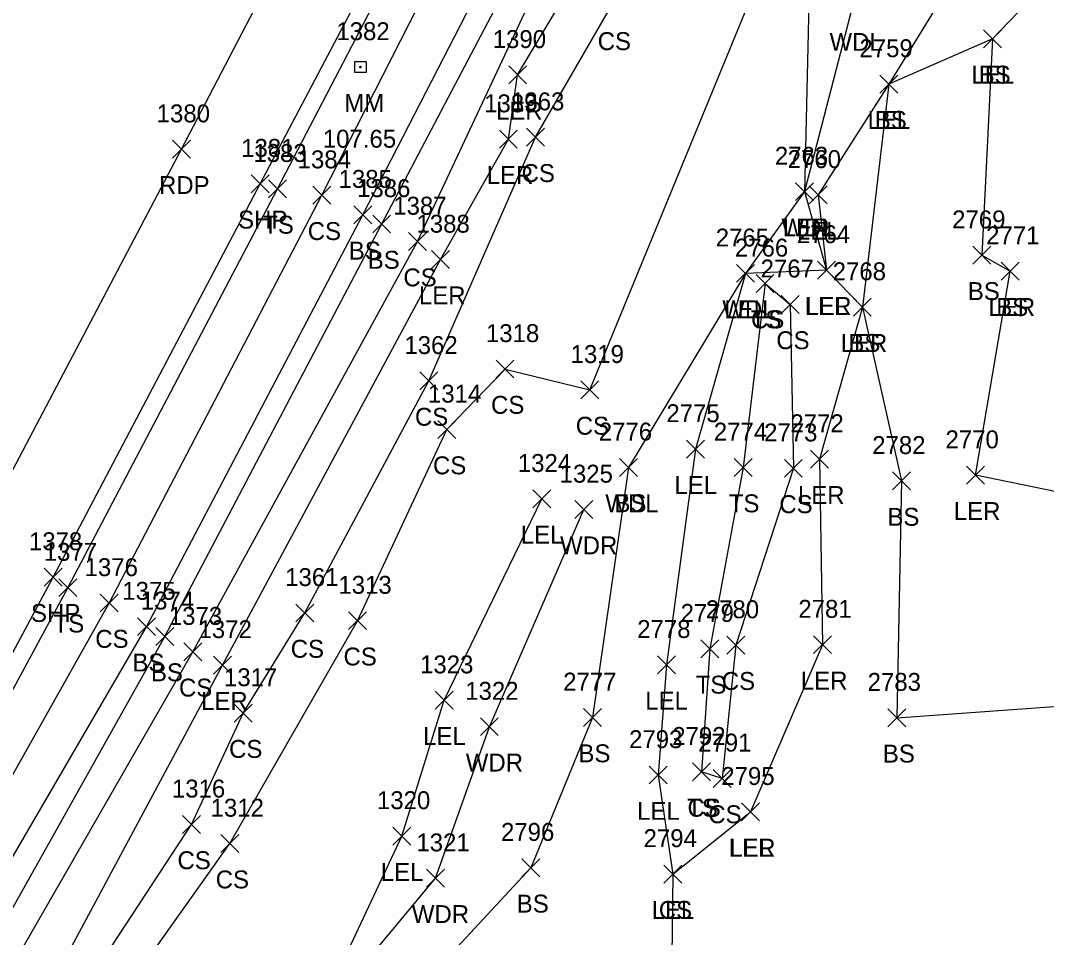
# Model space of a CAD drawing. Extents: x 1483143 to 1488182, y 802902 to 807581.
# Drawn here: x 1487426.2 to 1487540.6, y 805492.2 to 805594.5 of the extents above; entities that cross this region are included whole.
import ezdxf

# ---------------------------------------------------------------- set-up
doc = ezdxf.new("R2010")
doc.units = 0
for name, color, linetype in [('L_A', 7, 'Continuous'), ('L_I', 7, 'Continuous'), ('L_TIC', 7, 'Continuous'), ('LARO', 7, 'Continuous'), ('LAWA', 7, 'Continuous'), ('LELB', 7, 'Continuous'), ('P_A', 7, 'Continuous'), ('P_I', 7, 'Continuous'), ('P_TIC', 7, 'Continuous'), ('PET', 7, 'Continuous'), ('PSP', 7, 'Continuous'), ('S_A', 7, 'Continuous'), ('S_C', 7, 'Continuous'), ('S_I', 7, 'Continuous'), ('SRM', 7, 'Continuous')]:
    doc.layers.add(name, color=color, linetype=linetype)

msp = doc.modelspace()

# ---------------------------------------------------------------- linework, layer by layer
at = {"layer": 'L_TIC'}
for points in [[(1487533.63, 805591.48), (1487535.63, 805593.48)], [(1487535.63, 805591.48), (1487533.63, 805593.48)], [(1487533.63, 805591.48), (1487535.63, 805593.48)], [(1487535.63, 805591.48), (1487533.63, 805593.48)], [(1487480.64, 805587.45), (1487482.64, 805589.45)], [(1487482.64, 805587.45), (1487480.64, 805589.45)], [(1487522.05, 805586.43), (1487524.05, 805588.43)], [(1487524.05, 805586.43), (1487522.05, 805588.43)], [(1487522.05, 805586.43), (1487524.05, 805588.43)], [(1487524.05, 805586.43), (1487522.05, 805588.43)], [(1487479.6, 805580.28), (1487481.6, 805582.28)], [(1487481.6, 805580.28), (1487479.6, 805582.28)], [(1487482.64, 805580.5), (1487484.64, 805582.5)], [(1487484.64, 805580.5), (1487482.64, 805582.5)], [(1487453.84, 805574.74), (1487455.84, 805576.74)], [(1487455.84, 805574.74), (1487453.84, 805576.74)], [(1487512.65, 805574.43), (1487514.65, 805576.43)], [(1487514.65, 805574.43), (1487512.65, 805576.43)], [(1487512.65, 805574.43), (1487514.65, 805576.43)], [(1487514.65, 805574.43), (1487512.65, 805576.43)], [(1487458.78, 805574.03), (1487460.78, 805576.03)], [(1487460.78, 805574.03), (1487458.78, 805576.03)], [(1487514.17, 805574.06), (1487516.17, 805576.06)], [(1487516.17, 805574.06), (1487514.17, 805576.06)], [(1487463.36, 805571.85), (1487465.36, 805573.85)], [(1487465.36, 805571.85), (1487463.36, 805573.85)], [(1487465.47, 805570.82), (1487467.47, 805572.82)], [(1487467.47, 805570.82), (1487465.47, 805572.82)], [(1487469.45, 805568.86), (1487471.45, 805570.86)], [(1487471.45, 805568.86), (1487469.45, 805570.86)], [(1487532.43, 805567.33), (1487534.43, 805569.33)], [(1487534.43, 805567.33), (1487532.43, 805569.33)], [(1487472.04, 805566.85), (1487474.04, 805568.85)], [(1487474.04, 805566.85), (1487472.04, 805568.85)], [(1487506.05, 805565.31), (1487508.05, 805567.31)], [(1487508.05, 805565.31), (1487506.05, 805567.31)], [(1487506.05, 805565.31), (1487508.05, 805567.31)], [(1487508.05, 805565.31), (1487506.05, 805567.31)], [(1487515.1, 805565.68), (1487517.1, 805567.68)], [(1487517.1, 805565.68), (1487515.1, 805567.68)], [(1487515.1, 805565.68), (1487517.1, 805567.68)], [(1487517.1, 805565.68), (1487515.1, 805567.68)], [(1487535.6, 805565.55), (1487537.6, 805567.55)], [(1487537.6, 805565.55), (1487535.6, 805567.55)], [(1487535.6, 805565.55), (1487537.6, 805567.55)], [(1487537.6, 805565.55), (1487535.6, 805567.55)], [(1487508.24, 805564.18), (1487510.24, 805566.18)], [(1487510.24, 805564.18), (1487508.24, 805566.18)], [(1487508.24, 805564.18), (1487510.24, 805566.18)], [(1487510.24, 805564.18), (1487508.24, 805566.18)], [(1487511.06, 805561.85), (1487513.06, 805563.85)], [(1487513.06, 805561.85), (1487511.06, 805563.85)], [(1487519.1, 805561.54), (1487521.1, 805563.54)], [(1487521.1, 805561.54), (1487519.1, 805563.54)], [(1487519.1, 805561.54), (1487521.1, 805563.54)], [(1487521.1, 805561.54), (1487519.1, 805563.54)], [(1487479.23, 805554.64), (1487481.23, 805556.64)], [(1487481.23, 805554.64), (1487479.23, 805556.64)], [(1487470.74, 805553.31), (1487472.74, 805555.31)], [(1487472.74, 805553.31), (1487470.74, 805555.31)], [(1487488.68, 805552.31), (1487490.68, 805554.31)], [(1487490.68, 805552.31), (1487488.68, 805554.31)], [(1487472.75, 805547.89), (1487474.75, 805549.89)], [(1487474.75, 805547.89), (1487472.75, 805549.89)], [(1487500.49, 805545.71), (1487502.49, 805547.71)], [(1487502.49, 805545.71), (1487500.49, 805547.71)], [(1487514.33, 805544.58), (1487516.33, 805546.58)], [(1487516.33, 805544.58), (1487514.33, 805546.58)], [(1487493, 805543.66), (1487495, 805545.66)], [(1487495, 805543.66), (1487493, 805545.66)], [(1487493, 805543.66), (1487495, 805545.66)], [(1487495, 805543.66), (1487493, 805545.66)], [(1487505.79, 805543.65), (1487507.79, 805545.65)], [(1487507.79, 805543.65), (1487505.79, 805545.65)], [(1487511.4, 805543.56), (1487513.4, 805545.56)], [(1487513.4, 805543.56), (1487511.4, 805545.56)], [(1487523.46, 805542.15), (1487525.46, 805544.15)], [(1487525.46, 805542.15), (1487523.46, 805544.15)], [(1487531.73, 805542.79), (1487533.73, 805544.79)], [(1487533.73, 805542.79), (1487531.73, 805544.79)], [(1487483.35, 805540.15), (1487485.35, 805542.15)], [(1487485.35, 805540.15), (1487483.35, 805542.15)], [(1487488.01, 805538.96), (1487490.01, 805540.96)], [(1487490.01, 805538.96), (1487488.01, 805540.96)], [(1487430.45, 805530.24), (1487432.45, 805532.24)], [(1487432.45, 805530.24), (1487430.45, 805532.24)], [(1487435.07, 805528.53), (1487437.07, 805530.53)], [(1487437.07, 805528.53), (1487435.07, 805530.53)], [(1487456.88, 805527.42), (1487458.88, 805529.42)], [(1487458.88, 805527.42), (1487456.88, 805529.42)], [(1487462.77, 805526.56), (1487464.77, 805528.56)], [(1487464.77, 805526.56), (1487462.77, 805528.56)], [(1487439.22, 805525.89), (1487441.22, 805527.89)], [(1487441.22, 805525.89), (1487439.22, 805527.89)], [(1487441.28, 805524.8), (1487443.28, 805526.8)], [(1487443.28, 805524.8), (1487441.28, 805526.8)], [(1487504.98, 805523.83), (1487506.98, 805525.83)], [(1487506.98, 805523.83), (1487504.98, 805525.83)], [(1487514.66, 805523.88), (1487516.66, 805525.88)], [(1487516.66, 805523.88), (1487514.66, 805525.88)], [(1487444.41, 805523.09), (1487446.41, 805525.09)], [(1487446.41, 805523.09), (1487444.41, 805525.09)], [(1487502.09, 805523.42), (1487504.09, 805525.42)], [(1487504.09, 805523.42), (1487502.09, 805525.42)], [(1487447.72, 805521.61), (1487449.72, 805523.61)], [(1487449.72, 805521.61), (1487447.72, 805523.61)], [(1487497.24, 805521.63), (1487499.24, 805523.63)], [(1487499.24, 805521.63), (1487497.24, 805523.63)], [(1487472.45, 805517.68), (1487474.45, 805519.68)], [(1487474.45, 805517.68), (1487472.45, 805519.68)], [(1487450, 805516.25), (1487452, 805518.25)], [(1487452, 805516.25), (1487450, 805518.25)], [(1487477.48, 805514.73), (1487479.48, 805516.73)], [(1487479.48, 805514.73), (1487477.48, 805516.73)], [(1487488.98, 805515.76), (1487490.98, 805517.76)], [(1487490.98, 805515.76), (1487488.98, 805517.76)], [(1487522.95, 805515.73), (1487524.95, 805517.73)], [(1487524.95, 805515.73), (1487522.95, 805517.73)], [(1487522.95, 805515.73), (1487524.95, 805517.73)], [(1487524.95, 805515.73), (1487522.95, 805517.73)], [(1487496.33, 805509.34), (1487498.33, 805511.34)], [(1487498.33, 805509.34), (1487496.33, 805511.34)], [(1487501.15, 805509.69), (1487503.15, 805511.69)], [(1487503.15, 805509.69), (1487501.15, 805511.69)], [(1487501.15, 805509.69), (1487503.15, 805511.69)], [(1487503.15, 805509.69), (1487501.15, 805511.69)], [(1487503.47, 805508.96), (1487505.47, 805510.96)], [(1487505.47, 805508.96), (1487503.47, 805510.96)], [(1487506.62, 805505.23), (1487508.62, 805507.23)], [(1487508.62, 805505.23), (1487506.62, 805507.23)], [(1487506.62, 805505.23), (1487508.62, 805507.23)], [(1487508.62, 805505.23), (1487506.62, 805507.23)], [(1487444.24, 805503.83), (1487446.24, 805505.83)], [(1487446.24, 805503.83), (1487444.24, 805505.83)], [(1487467.72, 805502.53), (1487469.72, 805504.53)], [(1487469.72, 805502.53), (1487467.72, 805504.53)], [(1487448.51, 805501.69), (1487450.51, 805503.69)], [(1487450.51, 805501.69), (1487448.51, 805503.69)], [(1487482.1, 805498.99), (1487484.1, 805500.99)], [(1487484.1, 805498.99), (1487482.1, 805500.99)], [(1487471.47, 805497.82), (1487473.47, 805499.82)], [(1487473.47, 805497.82), (1487471.47, 805499.82)], [(1487497.95, 805498.29), (1487499.95, 805500.29)], [(1487499.95, 805498.29), (1487497.95, 805500.29)], [(1487497.95, 805498.29), (1487499.95, 805500.29)], [(1487499.95, 805498.29), (1487497.95, 805500.29)]]:
    msp.add_lwpolyline(points, dxfattribs=at)
at = {"layer": 'LARO'}
for points in [[(1487423.77, 805476.17), (1487448.72, 805522.61), (1487473.04, 805567.85), (1487480.6, 805581.28), (1487481.64, 805588.45), (1487490.08, 805602.57), (1487492.1, 805615.56), (1487501.67, 805631.76), (1487510.58, 805643.39), (1487515.16, 805650.67), (1487521.68, 805670.54)], [(1487553.51, 805539.5), (1487570.22, 805552.53), (1487590.58, 805565.95), (1487593.27, 805576.26), (1487589.04, 805592.63), (1487578.77, 805612.98), (1487577.04, 805623.26), (1487583.1, 805647.56), (1487579.43, 805649.82), (1487564.56, 805648.82), (1487556.92, 805624.92), (1487544.14, 805602.42), (1487534.63, 805592.48), (1487523.05, 805587.43), (1487515.17, 805575.06), (1487516.1, 805566.68), (1487507.05, 805566.31), (1487501.49, 805546.71), (1487498.24, 805522.63), (1487497.33, 805510.34), (1487498.95, 805499.29), (1487507.62, 805506.23)], [(1487514.22, 805599.68), (1487513.65, 805575.43), (1487516.1, 805566.68), (1487520.1, 805562.54), (1487515.33, 805545.58), (1487515.66, 805524.88), (1487507.62, 805506.23)], [(1487553.51, 805539.5), (1487532.73, 805543.79), (1487536.6, 805566.55)], [(1487458.8, 805482.34), (1487468.72, 805503.53), (1487473.45, 805518.68), (1487484.35, 805541.15)]]:
    msp.add_lwpolyline(points, dxfattribs=at)
at = {"layer": 'LAWA'}
for points in [[(1487519.02, 805596.14), (1487513.65, 805575.43), (1487507.05, 805566.31), (1487494, 805544.66)], [(1487458.8, 805482.34), (1487472.47, 805498.82), (1487478.48, 805515.73), (1487489.01, 805539.96)]]:
    msp.add_lwpolyline(points, dxfattribs=at)
at = {"layer": 'LELB'}
for points in [[(1487406.66, 805485.41), (1487431.45, 805531.24), (1487454.84, 805575.74), (1487473.75, 805612.05), (1487489.43, 805642.37), (1487507.64, 805678.53), (1487524.82, 805711.39), (1487541.86, 805746.09), (1487557.67, 805776.44), (1487575.49, 805812.01), (1487597.52, 805857.93), (1487620.62, 805906.82), (1487641.85, 805951.94), (1487662.18, 805996.35), (1487684.09, 806043.93), (1487694.42, 806066.95), (1487726.58, 806140.7), (1487745.85, 806185.55), (1487769.04, 806237.65), (1487788.58, 806284.85), (1487808.3, 806333.26), (1487827.52, 806379.6), (1487850.09, 806437.73)], [(1487410.04, 805483.24), (1487436.07, 805529.53), (1487459.78, 805575.03), (1487477.42, 805609.67), (1487492.45, 805639.09), (1487509.86, 805677.27), (1487528.68, 805708.85), (1487545.3, 805744.17), (1487561.79, 805774.32), (1487579.7, 805810.21), (1487602.04, 805856.31), (1487624.97, 805905.57), (1487645.72, 805950.02), (1487667.21, 805993.1), (1487687.16, 806043.23), (1487699.2, 806065.16), (1487730.65, 806138.87), (1487749.96, 806183.58), (1487772.93, 806235.17), (1487792.36, 806283.08), (1487812.9, 806331.5), (1487831.61, 806378.23), (1487855.61, 806436.65)], [(1487413.83, 805481.53), (1487440.22, 805526.89), (1487464.36, 805572.85), (1487481.71, 805606.55), (1487496.63, 805636.25), (1487514.9, 805673.97), (1487535.8, 805705.94), (1487549.07, 805741.59), (1487566.17, 805772.22), (1487583.99, 805807.69), (1487605.26, 805855.28), (1487629.33, 805903.01), (1487650.26, 805948.76), (1487670.48, 805991.25), (1487690.28, 806041.74), (1487702.22, 806061.37), (1487704.47, 806066.39), (1487735.28, 806136.71), (1487754, 806182.42), (1487776.55, 806233.47), (1487796.75, 806281.41), (1487816.88, 806330.25), (1487835.19, 806376.59), (1487859.78, 806434.97)], [(1487417, 805480.8), (1487442.28, 805525.8), (1487466.47, 805571.82), (1487483.84, 805604.86), (1487498.25, 805635.76), (1487518.24, 805671.86), (1487538.47, 805704.77), (1487552.2, 805739.67), (1487568.17, 805771.84), (1487585.97, 805806.76), (1487609.39, 805853.47), (1487632.34, 805900.81), (1487653.02, 805947.32), (1487672.59, 805990.01), (1487694.92, 806039.27), (1487707.45, 806059.25), (1487710.05, 806064.3), (1487737.97, 806135.43), (1487757.4, 806181.42), (1487778.76, 806231.94), (1487799.97, 806279.97), (1487818.92, 806329.91), (1487837.5, 806376), (1487863.45, 806433.38)], [(1487428.48, 805479.23), (1487445.24, 805504.83), (1487451, 805517.25), (1487457.88, 805528.42), (1487471.74, 805554.31), (1487483.64, 805581.5), (1487492.13, 805596.22), (1487504.57, 805614.88), (1487515.61, 805636.44), (1487523.33, 805664.03), (1487527.1, 805668), (1487534.05, 805680.73), (1487538.75, 805686.85), (1487544.76, 805692.45), (1487548.74, 805693.28), (1487553.89, 805708.06), (1487558.5, 805723.21), (1487562.96, 805732.39), (1487569.7, 805746.23), (1487572.43, 805748.36), (1487588.97, 805765.58), (1487591.12, 805760.32), (1487603.32, 805759.56)], [(1487438.06, 805486.56), (1487449.51, 805502.69), (1487463.77, 805527.56), (1487473.75, 805548.89), (1487480.23, 805555.64), (1487489.68, 805553.31), (1487531.36, 805654.66), (1487538.66, 805667.76), (1487544.44, 805685.95), (1487547.35, 805690.53), (1487553.51, 805690.65), (1487551.83, 805696.06), (1487556.39, 805700.08), (1487558.02, 805713.74), (1487569.17, 805725.52), (1487574.82, 805736.37), (1487607.32, 805758.13)], [(1487199.3, 805080.96), (1487209.02, 805107.06), (1487224.53, 805127.21), (1487240.95, 805152.24), (1487249.95, 805171.94), (1487269.65, 805210.5), (1487285.86, 805237.33), (1487303.36, 805267.84), (1487322.25, 805302.17), (1487347.45, 805347.07), (1487376.58, 805390.13), (1487398.58, 805433.78), (1487419.88, 805479.75), (1487445.41, 805524.09), (1487470.45, 805569.86), (1487486.06, 805603.16), (1487492.1, 805615.56), (1487500.68, 805632.42), (1487507.33, 805640.17), (1487520.3, 805671.34), (1487528.77, 805686.31), (1487539.17, 805698.49)], [(1487564.52, 805673.97), (1487563.22, 805648.26), (1487549.74, 805628.2), (1487535.27, 805607.28), (1487523.05, 805587.43), (1487520.1, 805562.54), (1487524.46, 805543.15), (1487523.95, 805516.73)], [(1487534.63, 805592.48), (1487533.43, 805568.33), (1487536.6, 805566.55)], [(1487509.24, 805565.18), (1487506.79, 805544.65), (1487503.09, 805524.42), (1487502.15, 805510.69)], [(1487509.24, 805565.18), (1487512.06, 805562.85), (1487512.4, 805544.56), (1487505.98, 805524.83), (1487504.47, 805509.96), (1487502.15, 805510.69)], [(1487494, 805544.66), (1487489.98, 805516.76), (1487483.1, 805499.99), (1487469.62, 805485.44), (1487459.73, 805470.37), (1487454.06, 805447.12), (1487466.58, 805438.47), (1487460.53, 805427.6), (1487458.79, 805393.78), (1487437.28, 805402.12), (1487422.27, 805383.88)], [(1487523.95, 805516.73), (1487545.65, 805518.28), (1487556.52, 805508.05)], [(1487498.95, 805499.29), (1487498.64, 805474.67), (1487497.23, 805443.74), (1487505.04, 805441.72), (1487510.17, 805435.4), (1487504.77, 805417.91), (1487493.48, 805388.2), (1487491.14, 805377.64), (1487487.41, 805369.48), (1487480.75, 805361.74), (1487474.3, 805355.43), (1487470.84, 805329.04), (1487477.5, 805318.33), (1487486.09, 805303.62), (1487460.83, 805297.42), (1487440.44, 805293.54)]]:
    msp.add_lwpolyline(points, dxfattribs=at)
at = {"layer": 'P_TIC'}
for points in [[(1487443.13, 805579.16), (1487445.13, 805581.16)], [(1487445.13, 805579.16), (1487443.13, 805581.16)], [(1487451.92, 805575.31), (1487453.92, 805577.31)], [(1487453.92, 805575.31), (1487451.92, 805577.31)], [(1487428.8, 805531.42), (1487430.8, 805533.42)], [(1487430.8, 805531.42), (1487428.8, 805533.42)]]:
    msp.add_lwpolyline(points, dxfattribs=at)
at = {"layer": 'PET'}
msp.add_lwpolyline([(1487396.33, 805490.41), (1487421.9, 805537.94), (1487444.13, 805580.16), (1487464.29, 805618.83), (1487479.8, 805648.39), (1487498.08, 805684.27), (1487514.57, 805717.15), (1487530.55, 805749.06), (1487547.16, 805782.47), (1487564.33, 805817.54), (1487585.71, 805863.32), (1487608.89, 805911.38), (1487630.35, 805956.68), (1487651.22, 806001.25), (1487672.63, 806048.33), (1487683.65, 806072.29), (1487715.61, 806144.47), (1487735.35, 806190.47), (1487757.48, 806241.03), (1487777.65, 806289.15), (1487798.25, 806337.46), (1487817.05, 806384.04), (1487839.67, 806441.4)], dxfattribs=at)
at = {"layer": 'PSP'}
msp.add_lwpolyline([(1487405.03, 805486.21), (1487429.8, 805532.42), (1487452.92, 805576.31), (1487472.37, 805613.24), (1487487.86, 805643.29), (1487506.35, 805679.4), (1487523.34, 805712.45), (1487540.38, 805746.64), (1487556.03, 805777.85), (1487573.44, 805813.27), (1487595.34, 805859.04), (1487618.37, 805906.67), (1487640.09, 805952.42), (1487660.18, 805997.21), (1487682.38, 806044.71), (1487693.04, 806068.56), (1487725.12, 806141.19), (1487744.39, 806185.87), (1487766.81, 806238.55), (1487786.8, 806285.64), (1487806.77, 806333.93), (1487825.55, 806380.21), (1487847.81, 806437.56)], dxfattribs=at)
at = {"layer": 'SRM'}
msp.add_lwpolyline([(1487463.48, 805589.96), (1487464.73, 805589.96), (1487464.73, 805588.71), (1487463.48, 805588.71)], close=True, dxfattribs=at)
msp.add_circle((1487464.1, 805589.33), 0.0833, dxfattribs=at)

# ---------------------------------------------------------------- texts
at = {"layer": 'L_A'}
for s, p in [('CS', (1487490.57, 805591.22)), ('WDL', (1487516.44, 805591.14)), ('LEL', (1487532.27, 805587.48)), ('BS', (1487533.08, 805587.48)), ('LER', (1487479.22, 805583.45)), ('LEL', (1487520.68, 805582.43)), ('BS', (1487521.49, 805582.43)), ('CS', (1487482.08, 805576.5)), ('LER', (1487478.18, 805576.28)), ('TS', (1487453.25, 805570.74)), ('CS', (1487458.22, 805570.03)), ('WDL', (1487511.07, 805570.43)), ('LER', (1487511.23, 805570.43)), ('LEL', (1487512.8, 805570.06)), ('BS', (1487462.8, 805567.85)), ('BS', (1487464.91, 805566.82)), ('CS', (1487468.89, 805564.86)), ('LER', (1487470.62, 805562.85)), ('BS', (1487531.87, 805563.33)), ('LER', (1487513.68, 805561.68)), ('LEL', (1487513.74, 805561.68)), ('BS', (1487535.04, 805561.55)), ('WDL', (1487504.47, 805561.31)), ('LEL', (1487504.69, 805561.31)), ('LER', (1487534.18, 805561.55)), ('TS', (1487507.65, 805560.18)), ('CS', (1487507.68, 805560.18)), ('CS', (1487510.5, 805557.85)), ('LER', (1487517.68, 805557.54)), ('BS', (1487518.54, 805557.54)), ('CS', (1487478.67, 805550.64)), ('CS', (1487470.18, 805549.31)), ('CS', (1487488.12, 805548.31)), ('CS', (1487472.19, 805543.89)), ('LEL', (1487499.13, 805541.71)), ('LER', (1487512.91, 805540.58)), ('WDL', (1487491.42, 805539.66)), ('BS', (1487492.44, 805539.66)), ('TS', (1487505.2, 805539.65)), ('CS', (1487510.84, 805539.56)), ('LER', (1487530.31, 805538.79)), ('BS', (1487522.9, 805538.15)), ('LEL', (1487481.99, 805536.15)), ('WDR', (1487486.37, 805534.96)), ('TS', (1487429.86, 805526.24)), ('CS', (1487434.51, 805524.53)), ('CS', (1487456.32, 805523.42)), ('BS', (1487438.66, 805521.89)), ('CS', (1487462.21, 805522.56)), ('BS', (1487440.72, 805520.8)), ('TS', (1487501.5, 805519.42)), ('CS', (1487504.42, 805519.83)), ('LER', (1487513.24, 805519.88)), ('CS', (1487443.85, 805519.09)), ('LER', (1487446.31, 805517.61)), ('LEL', (1487495.88, 805517.63)), ('LEL', (1487471.09, 805513.68)), ('CS', (1487449.44, 805512.25)), ('BS', (1487488.42, 805511.76)), ('BS', (1487522.39, 805511.73)), ('BS', (1487522.39, 805511.73)), ('WDR', (1487475.85, 805510.73)), ('TS', (1487500.56, 805505.69)), ('CS', (1487500.59, 805505.69)), ('LEL', (1487494.97, 805505.34)), ('CS', (1487502.91, 805504.96)), ('LER', (1487505.2, 805501.23)), ('LEL', (1487505.26, 805501.23)), ('CS', (1487443.68, 805499.83)), ('CS', (1487447.95, 805497.69)), ('LEL', (1487466.36, 805498.53)), ('BS', (1487481.54, 805494.99)), ('LEL', (1487496.59, 805494.29)), ('CS', (1487497.39, 805494.29)), ('WDR', (1487469.83, 805493.82))]:
    msp.add_text(s, height=2, dxfattribs=at).set_placement(p)
at = {"layer": 'L_I'}
for s, p in [('1390', (1487478.86, 805591.45)), ('2759', (1487519.78, 805590.43)), ('2759', (1487519.78, 805590.43)), ('1363', (1487480.9, 805584.5)), ('1389', (1487477.9, 805584.28)), ('1383', (1487452.15, 805578.74)), ('1384', (1487457.09, 805578.03)), ('2763', (1487510.34, 805578.43)), ('2763', (1487510.34, 805578.43)), ('2760', (1487511.77, 805578.06)), ('1385', (1487461.66, 805575.85)), ('1386', (1487463.72, 805574.82)), ('1387', (1487467.76, 805572.86)), ('1388', (1487470.35, 805570.85)), ('2769', (1487530.12, 805571.33)), ('2764', (1487512.79, 805569.68)), ('2764', (1487512.79, 805569.68)), ('2771', (1487533.91, 805569.55)), ('2771', (1487533.91, 805569.55)), ('2765', (1487503.74, 805569.31)), ('2765', (1487503.74, 805569.31)), ('2766', (1487505.88, 805568.18)), ('2766', (1487505.88, 805568.18)), ('2767', (1487508.75, 805565.85)), ('2768', (1487516.79, 805565.54)), ('2768', (1487516.79, 805565.54)), ('1318', (1487478.1, 805558.64)), ('1362', (1487469, 805557.31)), ('1319', (1487487.55, 805556.31)), ('1314', (1487471.63, 805551.89)), ('2775', (1487498.23, 805549.71)), ('2772', (1487512.07, 805548.58)), ('2776', (1487490.69, 805547.66)), ('2776', (1487490.69, 805547.66)), ('2774', (1487503.53, 805547.65)), ('2773', (1487509.14, 805547.56)), ('2770', (1487529.38, 805546.79)), ('2782', (1487521.2, 805546.15)), ('1324', (1487481.66, 805544.15)), ('1325', (1487486.32, 805542.96)), ('1377', (1487428.76, 805534.24)), ('1376', (1487433.32, 805532.53)), ('1361', (1487455.7, 805531.42)), ('1375', (1487437.53, 805529.89)), ('1313', (1487461.64, 805530.56)), ('1374', (1487439.59, 805528.8)), ('2779', (1487499.82, 805527.42)), ('2780', (1487502.63, 805527.83)), ('2781', (1487512.96, 805527.88)), ('1373', (1487442.72, 805527.09)), ('1372', (1487446.03, 805525.61)), ('2778', (1487494.98, 805525.63)), ('1323', (1487470.75, 805521.68)), ('1317', (1487448.87, 805520.25)), ('2777', (1487486.72, 805519.76)), ('2783', (1487520.69, 805519.73)), ('2783', (1487520.69, 805519.73)), ('1322', (1487475.79, 805518.73)), ('2792', (1487498.89, 805513.69)), ('2792', (1487498.89, 805513.69)), ('2793', (1487494.07, 805513.34)), ('2791', (1487501.78, 805512.96)), ('2795', (1487504.36, 805509.23)), ('2795', (1487504.36, 805509.23)), ('1316', (1487443.06, 805507.83)), ('1312', (1487447.38, 805505.69)), ('1320', (1487465.94, 805506.53)), ('2796', (1487479.78, 805502.99)), ('2794', (1487495.69, 805502.29)), ('2794', (1487495.69, 805502.29)), ('1321', (1487470.34, 805501.82))]:
    msp.add_text(s, height=2, dxfattribs=at).set_placement(p)
at = {"layer": 'P_A'}
for s, p in [('RDP', (1487441.62, 805575.16)), ('SHP', (1487450.45, 805571.31)), ('SHP', (1487427.34, 805527.42))]:
    msp.add_text(s, height=2, dxfattribs=at).set_placement(p)
at = {"layer": 'P_I'}
for s, p in [('1380', (1487441.36, 805583.16)), ('1381', (1487450.79, 805579.31)), ('1378', (1487427.11, 805535.42))]:
    msp.add_text(s, height=2, dxfattribs=at).set_placement(p)
at = {"layer": 'S_A'}
msp.add_text('MM', height=2, dxfattribs=at).set_placement((1487462.29, 805584.33))
at = {"layer": 'S_C'}
msp.add_text('107.65', height=2, dxfattribs=at).set_placement((1487459.9, 805580.33))
at = {"layer": 'S_I'}
msp.add_text('1382', height=2, dxfattribs=at).set_placement((1487461.41, 805592.33))

doc.saveas('drawing.dxf')
